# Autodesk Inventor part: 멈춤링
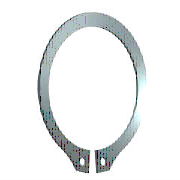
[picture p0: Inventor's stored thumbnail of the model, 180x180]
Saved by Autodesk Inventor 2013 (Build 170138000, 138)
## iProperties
IsCustomPart: 0
Created: 2009-02
Part Number: 멈춤링
Material: 강, 연강
Description: 리테이닝 링(C형)
Document SubType Name: Modeling
Standard: KS B 1336
Designer: KYOUNG IL JANG
Standards Organization: KS
Language: ko-KR
Size Designation: 22 x 1.2
Categories: <MemberInstance><Categories><Category DisplayName="샤프트 부품" InternalName="7f7aeb1f-a693-4053-b835-cee3144e0d98" Mnemonic="SHFT"><Category DisplayName="써클립" Inter
Density: 7.86 g/cm^3
Mass: 1.8286 g
Surface Area: 5.91219 cm^2
Volume: 0.232646 cm^3
Author: KYOUNG IL JANG
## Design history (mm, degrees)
sketch "스케치1"
  geometry: L1 (-6, 0)-(6, 0) reference; L2 (0, 20.189)-(0, -80.536) reference; L3 (-48.09, 0)-(48.09, 0) reference; L4 (-0.5, -21.488)-(-0.5, -25.588); L5 (-0.5, -6.54)-(-0.5, -13.29); L6 (-2.795, 2.7)-(3.672, 2.7); L7 (0.5, -6.54)-(0.5, -13.29); L8 (0.5, -21.488)-(0.5, -25.588); C1 r 1 at (-2, -23.437); C2 r 1 at (2, -23.437); A1 r 10.5 centre (0, -11) between (0.5, -21.488) and (-0.5, -21.488); A2 r 13.025 centre (0, -10.325) between (5.149, -22.289) and (-5.149, -22.289); A3 r 14.597 centre (0, -11) between (-2.318, -25.411) and (-0.5, -25.588); A4 r 2 centre (-2, -23.437) between (-3.97, -23.781) and (-2.318, -25.411); A5 r 2 centre (-5.94, -24.126) between (-3.97, -23.781) and (-5.149, -22.289); A6 r 2 centre (5.94, -24.126) between (5.149, -22.289) and (3.97, -23.781); A7 r 2 centre (2, -23.437) between (2.318, -25.411) and (3.97, -23.781); A8 r 14.597 centre (0, -11) between (0.5, -25.588) and (2.318, -25.411)
  constraints: 16 point on circle, 12 end point, 10 centre point, 9 symmetric about line, 5 point on line, 4 tangent, 3 coincident, 2 horizontal, 1 perpendicular, 1 vertical, 5 other
  dimensions: "d0" = 21 diameter of A1 (= ND); "d1" = 4.1 distance of L4.end L4.start (= SRB2); "d6" = 0.5 distance between parallel lines of L2 L5 (= 0.25 x SD5); "d7" = 2.7 distance between parallel lines of L6 L3 (= SRB1); "d8" = 0.675 distance of A1.centre A2.centre (= 0.25 x SRB1); "d9" = 2 radius of A4 (= SD5); "d10" = 2 radius of A5 (= SD5); "d11" = 1.5 distance from line of L4 A4.centre (= 0.75 x SD5); "d12" = 2 diameter of C1 (= SD5); "d13" = 2 diameter of C2 (= SD5); "d14" = 11 distance from line of A1.centre L1 (= 0.5 x WD)
extrude "본체" new body sketch "스케치1" distance "d2" = 1.2 (= SD); taper "d3" = 0 deg
workaxis "Work Axis1"
workplane "Work Plane1"
body "Solid1"
other parameters: "WD" = 22 (= WDMIN) [user parameter; used in 1 equation term], "SD" = 1.2 [user parameter; used in 1 equation term], "SRB1" = 2.7 [user parameter; used in 2 equation terms], "ND" = 21 [user parameter; used in 1 equation term], "SRB2" = 4.1 [user parameter; used in 1 equation term], "SD5" = 2 [user parameter; used in 6 equation terms], "d15" = 0, "d16" = 0, "d17" = 0, "d41" = 0, "d42" = 0, "WDMIN" = 22 [user parameter; used in 1 equation term], "SD3" = 20.5 [user parameter], "WDMAX" = 24 [user parameter]
